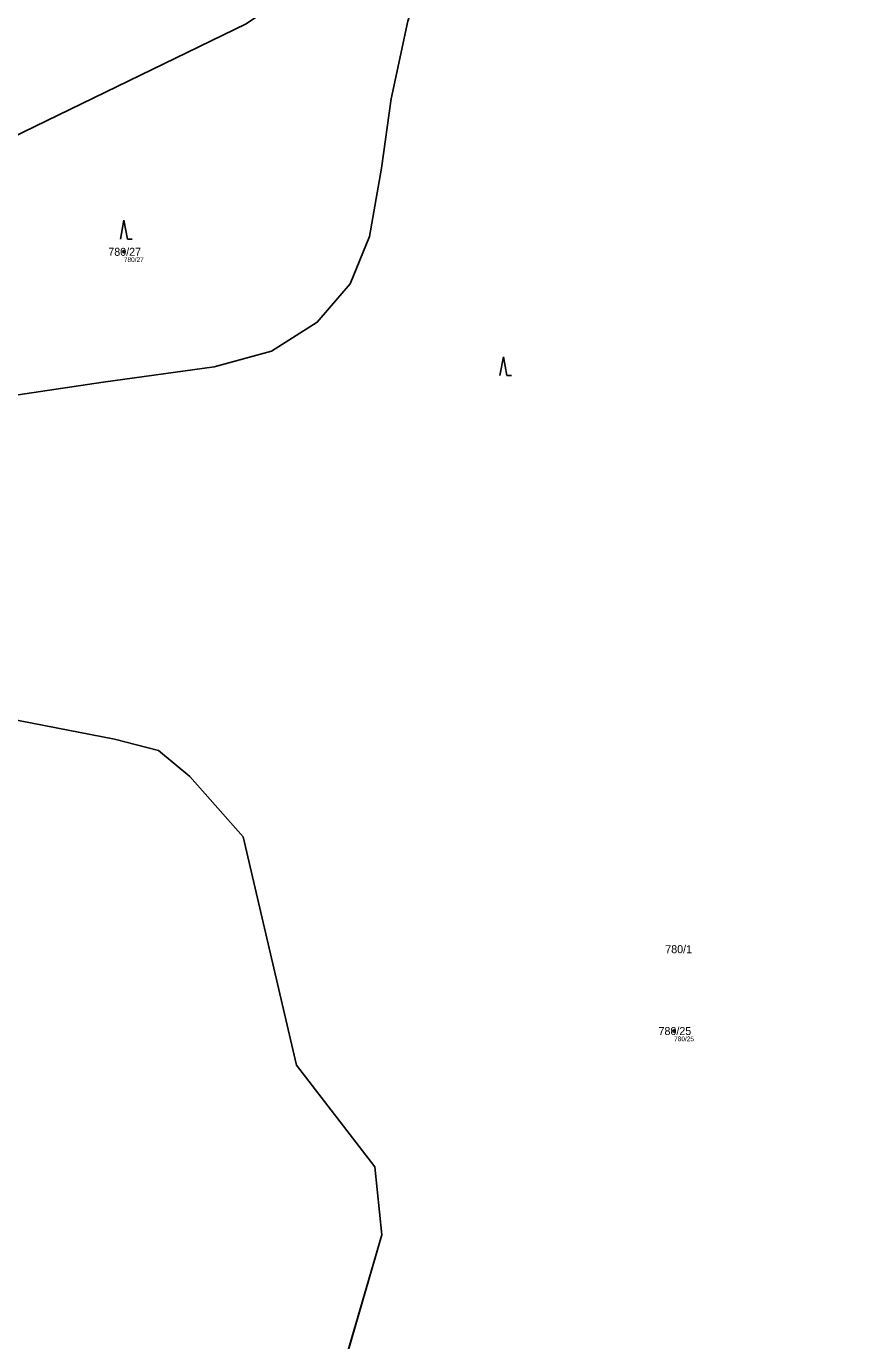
# Model space of a CAD drawing. Extents: x -754731 to -751381, y -1060564 to -1058101.
# Drawn here: x -754026.7 to -753851.6, y -1059945.8 to -1059666.5 of the extents above; entities that cross this region are included whole.
import ezdxf

# ---------------------------------------------------------------- set-up
doc = ezdxf.new("R2010")
doc.units = 0
for name, color, linetype in [('Definiční body', 7, 'Continuous'), ('Hranice parcel', 7, 'Continuous'), ('Parcelní čísla', 7, 'Continuous'), ('Polygon ku', 7, 'Continuous'), ('Polygon parcely', 7, 'Continuous'), ('Značky kultur', 7, 'Continuous')]:
    doc.layers.add(name, color=color, linetype=linetype)

msp = doc.modelspace()

# ---------------------------------------------------------------- linework, layer by layer
at = {"layer": 'Definiční body'}
for centre in [(-754005.96, -1059714.41), (-753889.07, -1059879.97)]:
    msp.add_circle(centre, 0.25, dxfattribs=at)
at = {"layer": 'Hranice parcel'}
for p, q in [((-753952.62, -1059908.83), (-753951.13, -1059923.3)), ((-753951.13, -1059923.3), (-753961.69, -1059959.37))]:
    msp.add_line(p, q, dxfattribs=at)
for points in [[(-754044.94, -1059697.47), (-753979.96, -1059665.98), (-753942.59, -1059640.69)], [(-753938.11, -1059644.76), (-753940.81, -1059651.77), (-753943.76, -1059659.43), (-753945.63, -1059665.43), (-753949.16, -1059681.94), (-753951.22, -1059696.66), (-753953.77, -1059711.18), (-753957.9, -1059721.21), (-753964.88, -1059729.37), (-753974.59, -1059735.53), (-753986.77, -1059738.88), (-754010.35, -1059742.12), (-754037.05, -1059746.04), (-754054.73, -1059750.96), (-754067.98, -1059757.93), (-754078.09, -1059767.94), (-754089.54, -1059784.53)], [(-754092, -1059803.1), (-754040.47, -1059811.66), (-754007.98, -1059817.95)], [(-754007.98, -1059817.95), (-753998.57, -1059820.39), (-753991.93, -1059825.91), (-753980.63, -1059838.74)], [(-753980.63, -1059838.74), (-753969.26, -1059887.23), (-753952.62, -1059908.83)]]:
    msp.add_lwpolyline(points, dxfattribs=at)
at = {"layer": 'Polygon ku'}
msp.add_lwpolyline([(-754311.62, -1059836.57), (-754257.25, -1059898.19), (-754240.56, -1059926.64), (-754231.59, -1059941.49), (-754229.9, -1059944.15), (-754215.13, -1059956.29), (-754199.75, -1059936.66), (-754186.4, -1059921.2), (-754180.24, -1059913.84), (-754107.69, -1059809.78), (-754099.83, -1059806.43), (-754092, -1059803.1), (-754040.47, -1059811.66), (-754007.98, -1059817.95), (-753998.57, -1059820.39), (-753991.93, -1059825.91), (-753980.63, -1059838.74), (-753969.26, -1059887.23), (-753952.62, -1059908.83), (-753951.13, -1059923.3), (-753961.69, -1059959.37)], dxfattribs=at)
at = {"layer": 'Polygon parcely'}
for points in [[(-754096.92, -1059691.69), (-754075, -1059691.19), (-754055.04, -1059694.94), (-754044.94, -1059697.47), (-753979.96, -1059665.98), (-753942.59, -1059640.69), (-754030.96, -1059628.13), (-754042.49, -1059656.51), (-754103.34, -1059671.44), (-754132.23, -1059688.25), (-754140.91, -1059700.83), (-754119.28, -1059692.08)], [(-754073.51, -1059738.36), (-754091.25, -1059783.39), (-754089.54, -1059784.53), (-754078.09, -1059767.94), (-754067.98, -1059757.93), (-754054.73, -1059750.96), (-754037.05, -1059746.04), (-754010.35, -1059742.12), (-753986.77, -1059738.88), (-753974.59, -1059735.53), (-753964.88, -1059729.37), (-753957.9, -1059721.21), (-753953.77, -1059711.18), (-753951.22, -1059696.66), (-753949.16, -1059681.94), (-753945.63, -1059665.43), (-753943.76, -1059659.43), (-753940.81, -1059651.77), (-753938.11, -1059644.76), (-753942.59, -1059640.69), (-753979.96, -1059665.98), (-754044.94, -1059697.47), (-754039.95, -1059705.56)]]:
    msp.add_lwpolyline(points, close=True, dxfattribs=at)
for points in [[(-753943.76, -1059659.43), (-753945.63, -1059665.43), (-753949.16, -1059681.94), (-753951.22, -1059696.66), (-753953.77, -1059711.18), (-753957.9, -1059721.21), (-753964.88, -1059729.37), (-753974.59, -1059735.53), (-753986.77, -1059738.88), (-754010.35, -1059742.12), (-754037.05, -1059746.04), (-754054.73, -1059750.96), (-754067.98, -1059757.93), (-754078.09, -1059767.94)], [(-754078.09, -1059767.94), (-754089.54, -1059784.53), (-754084.8, -1059787.7), (-754089.56, -1059801.58), (-754092, -1059803.1), (-754040.47, -1059811.66), (-754007.98, -1059817.95), (-753998.57, -1059820.39), (-753991.93, -1059825.91), (-753980.63, -1059838.74), (-753969.26, -1059887.23), (-753952.62, -1059908.83), (-753951.13, -1059923.3), (-753961.69, -1059959.37), (-753962.49, -1059982.31), (-753949.24, -1060018.62), (-753939.57, -1060031.16), (-753916.48, -1060046.8), (-753888.5, -1060070.35), (-753881.17, -1060074.16), (-753857.16, -1060077.78), (-753838.12, -1060085.32)]]:
    msp.add_lwpolyline(points, dxfattribs=at)
at = {"layer": 'Značky kultur'}
for p, q in [((-754005.96, -1059707.71), (-754006.71, -1059711.71)), ((-754005.21, -1059711.71), (-754005.96, -1059707.71)), ((-754005.21, -1059711.71), (-754004.21, -1059711.71)), ((-753925.33, -1059736.72), (-753926.08, -1059740.72)), ((-753924.58, -1059740.72), (-753925.33, -1059736.72)), ((-753924.58, -1059740.72), (-753923.58, -1059740.72))]:
    msp.add_line(p, q, dxfattribs=at)

# ---------------------------------------------------------------- texts
at = {"layer": 'Definiční body'}
for s, p in [('780/27', (-754005.96, -1059716.57)), ('780/25', (-753889.07, -1059882.13))]:
    msp.add_text(s, height=1, dxfattribs=at).set_placement(p)
at = {"layer": 'Parcelní čísla'}
for s, p in [('780/27', (-754009.27, -1059715.26)), ('780/1', (-753890.95, -1059863.43)), ('780/25', (-753892.38, -1059880.82))]:
    msp.add_text(s, height=1.7, dxfattribs=at).set_placement(p)

doc.saveas('drawing.dxf')
